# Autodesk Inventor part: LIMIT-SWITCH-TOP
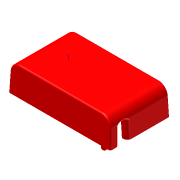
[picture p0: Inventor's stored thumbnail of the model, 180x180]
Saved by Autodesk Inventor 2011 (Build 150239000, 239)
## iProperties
Created: 2007-08
Part Number: LIMIT-SWITCH-TOP
Material: ABS Plastic
Document SubType Name: Modeling
Designer: Tyler
Density: 1.06 g/cm^3
Author: Tyler
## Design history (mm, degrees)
feature "Base1"
body "Solid1"
